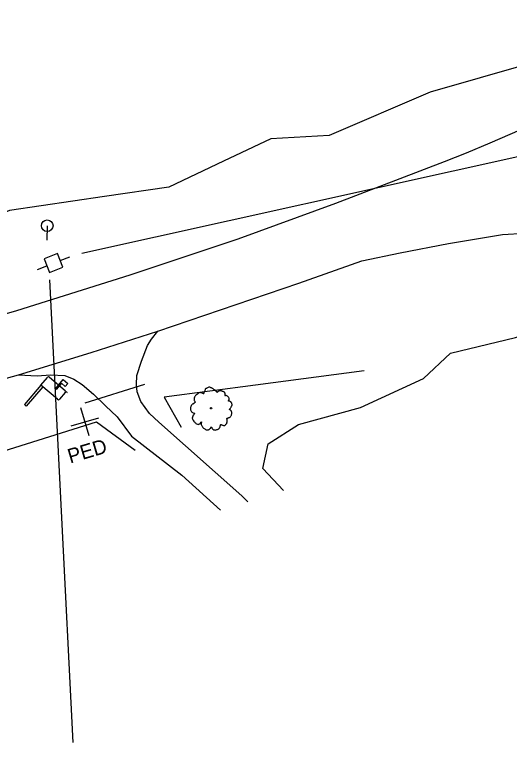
# Model space of a CAD drawing. Extents: x 2076109 to 2080761, y 592812 to 596750.
# Drawn here: x 2076543.2 to 2076714.3, y 595263.5 to 595514.8 of the extents above; entities that cross this region are included whole.
import ezdxf

# ---------------------------------------------------------------- set-up
doc = ezdxf.new("R2010")
doc.units = 0
for name, color, linetype in [('RD_EX_BldgApp', 7, 'Continuous'), ('RD_EX_DR_Pipe', 7, 'Continuous'), ('RD_EX_Driveway', 7, 'Continuous'), ('RD_EX_Fence_Other', 7, 'Continuous'), ('RD_EX_Misc', 7, 'Continuous'), ('RD_EX_Misc_txCode', 7, 'Continuous'), ('RD_EX_Road', 7, 'Continuous'), ('RD_EX_UT', 7, 'Continuous'), ('RD_EX_VEG', 7, 'Continuous')]:
    doc.layers.add(name, color=color, linetype=linetype)

msp = doc.modelspace()

# ---------------------------------------------------------------- linework, layer by layer
at = {"layer": 'RD_EX_BldgApp'}
for p, q in [((2076552.33, 595386.83), (2076554.6, 595389.5)), ((2076552.33, 595386.83), (2076554.6, 595389.5)), ((2076555.3, 595389.55), (2076560.69, 595384.98)), ((2076555.3, 595389.55), (2076560.69, 595384.98)), ((2076557.35, 595385.57), (2076560.06, 595388.76)), ((2076557.35, 595385.57), (2076560.06, 595388.76)), ((2076560.06, 595388.76), (2076561.63, 595387.43)), ((2076560.06, 595388.76), (2076561.63, 595387.43)), ((2076552.33, 595386.83), (2076546.62, 595380.11)), ((2076552.33, 595386.83), (2076546.62, 595380.11)), ((2076552.97, 595386.29), (2076547.26, 595379.57)), ((2076552.97, 595386.29), (2076547.26, 595379.57)), ((2076558.1, 595381.93), (2076552.33, 595386.83)), ((2076558.1, 595381.93), (2076552.33, 595386.83)), ((2076557.64, 595385.32), (2076557.35, 595385.57)), ((2076557.64, 595385.32), (2076557.35, 595385.57)), ((2076559.48, 595387.48), (2076557.64, 595385.32)), ((2076559.48, 595387.48), (2076557.64, 595385.32)), ((2076560.75, 595386.4), (2076559.48, 595387.48)), ((2076560.75, 595386.4), (2076559.48, 595387.48)), ((2076561.63, 595387.43), (2076560.75, 595386.4)), ((2076561.63, 595387.43), (2076560.75, 595386.4)), ((2076560.74, 595384.27), (2076558.8, 595381.99)), ((2076560.74, 595384.27), (2076558.8, 595381.99)), ((2076560.74, 595384.27), (2076561.07, 595384.65)), ((2076560.74, 595384.27), (2076561.07, 595384.65)), ((2076561.07, 595384.65), (2076561.45, 595384.33)), ((2076561.07, 595384.65), (2076561.45, 595384.33)), ((2076561.45, 595384.33), (2076561.29, 595384.14)), ((2076561.45, 595384.33), (2076561.29, 595384.14)), ((2076546.62, 595380.11), (2076547.26, 595379.57)), ((2076546.62, 595380.11), (2076547.26, 595379.57))]:
    msp.add_line(p, q, dxfattribs=at)
for centre, start, end in [((2076554.98, 595389.17), 49.6274, 139.6274), ((2076554.98, 595389.17), 49.6274, 139.6274), ((2076560.36, 595384.6), 319.6274, 49.6274), ((2076560.36, 595384.6), 319.6274, 49.6274), ((2076558.42, 595382.31), 229.6274, 319.6274), ((2076558.42, 595382.31), 229.6274, 319.6274)]:
    msp.add_arc(centre, 0.5, start, end, dxfattribs=at)
at = {"layer": 'RD_EX_DR_Pipe'}
msp.add_line((2076567.58, 595380.75), (2076588.2, 595387.21), dxfattribs=at)
msp.add_line((2076567.58, 595380.75), (2076588.2, 595387.21), dxfattribs=at)
at = {"layer": 'RD_EX_Driveway'}
msp.add_line((2076621.8, 595348.66), (2076623.83, 595346.57), dxfattribs=at)
msp.add_line((2076621.8, 595348.66), (2076623.83, 595346.57), dxfattribs=at)
for points in [[(2076621.8, 595348.66), (2076593.12, 595374.05), (2076589.9, 595376.98), (2076586.89, 595381.15), (2076585.6, 595384.51), (2076585.32, 595387.06), (2076585.46, 595390.21), (2076587.11, 595395.1), (2076589.17, 595400.48), (2076590.53, 595402.7), (2076592.75, 595405.46)], [(2076621.8, 595348.66), (2076593.12, 595374.05), (2076589.9, 595376.98), (2076586.89, 595381.15), (2076585.6, 595384.51), (2076585.32, 595387.06), (2076585.46, 595390.21), (2076587.11, 595395.1), (2076589.17, 595400.48), (2076590.53, 595402.7), (2076592.75, 595405.46)], [(2076544.59, 595390.37), (2076551.01, 595389.99), (2076555.66, 595390.36), (2076560.64, 595390.19), (2076563.66, 595388.87), (2076566.6, 595387.01), (2076570.56, 595383.69), (2076574.69, 595379.72), (2076578.65, 595375.85), (2076583.62, 595369.22), (2076601.04, 595355.7), (2076614.37, 595343.62)], [(2076544.59, 595390.37), (2076551.01, 595389.99), (2076555.66, 595390.36), (2076560.64, 595390.19), (2076563.66, 595388.87), (2076566.6, 595387.01), (2076570.56, 595383.69), (2076574.69, 595379.72), (2076578.65, 595375.85), (2076583.62, 595369.22), (2076601.04, 595355.7), (2076614.37, 595343.62)]]:
    msp.add_lwpolyline(points, dxfattribs=at)
at = {"layer": 'RD_EX_Fence_Other'}
for points in [[(2076664.12, 595391.78), (2076626.56, 595386.87), (2076594.95, 595382.67), (2076600.79, 595372.35)], [(2076664.12, 595391.78), (2076626.56, 595386.87), (2076594.95, 595382.67), (2076600.79, 595372.35)], [(2076413.91, 595332.33), (2076446.57, 595337.77), (2076456.21, 595339.99), (2076485.43, 595347.34), (2076504.69, 595353.19), (2076571.51, 595374.19), (2076584.94, 595364.39)], [(2076413.91, 595332.33), (2076446.57, 595337.77), (2076456.21, 595339.99), (2076485.43, 595347.34), (2076504.69, 595353.19), (2076571.51, 595374.19), (2076584.94, 595364.39)]]:
    msp.add_lwpolyline(points, dxfattribs=at)
at = {"layer": 'RD_EX_Misc'}
for p, q in [((2076569, 595369.35), (2076566.17, 595378.94)), ((2076569, 595369.35), (2076566.17, 595378.94)), ((2076562.79, 595372.73), (2076572.38, 595375.56)), ((2076562.79, 595372.73), (2076572.38, 595375.56))]:
    msp.add_line(p, q, dxfattribs=at)
at = {"layer": 'RD_EX_Road'}
for points in [[(2076707.59, 595470.49), (2076721.43, 595476.47)], [(2076707.59, 595470.49), (2076721.43, 595476.47)], [(2076404.77, 595376.23), (2076425.66, 595381.19), (2076454.7, 595388.18), (2076480.11, 595394.8), (2076514.19, 595403.96), (2076543.98, 595412.58), (2076583.19, 595424.9), (2076620.49, 595437.36), (2076654.29, 595449.62), (2076691.86, 595464.03), (2076699.44, 595467.03), (2076707.59, 595470.49)], [(2076404.77, 595376.23), (2076425.66, 595381.19), (2076454.7, 595388.18), (2076480.11, 595394.8), (2076514.19, 595403.96), (2076543.98, 595412.58), (2076583.19, 595424.9), (2076620.49, 595437.36), (2076654.29, 595449.62), (2076691.86, 595464.03), (2076699.44, 595467.03), (2076707.59, 595470.49)], [(2076409.15, 595355.14), (2076418.82, 595357.38), (2076452.18, 595365.54), (2076478.97, 595372.37), (2076513.39, 595381.71), (2076544.59, 595390.37), (2076569.72, 595398.06), (2076592.75, 595405.46), (2076641.5, 595422.06), (2076663.28, 595429.78), (2076676.52, 595432.55), (2076693.19, 595435.72), (2076711.91, 595438.8), (2076719.56, 595439.35)], [(2076409.15, 595355.14), (2076418.82, 595357.38), (2076452.18, 595365.54), (2076478.97, 595372.37), (2076513.39, 595381.71), (2076544.59, 595390.37), (2076569.72, 595398.06), (2076592.75, 595405.46), (2076641.5, 595422.06), (2076663.28, 595429.78), (2076676.52, 595432.55), (2076693.19, 595435.72), (2076711.91, 595438.8), (2076719.56, 595439.35)]]:
    msp.add_lwpolyline(points, dxfattribs=at)
at = {"layer": 'RD_EX_UT'}
for p, q in [((2076566.44, 595432.36), (2076937.84, 595514.77)), ((2076566.44, 595432.36), (2076937.84, 595514.77)), ((2076554.51, 595441.88), (2076554.35, 595436.88)), ((2076554.51, 595441.88), (2076554.35, 595436.88)), ((2076558.08, 595432.23), (2076553.43, 595430.4)), ((2076558.08, 595432.23), (2076553.43, 595430.4)), ((2076559.92, 595427.58), (2076558.08, 595432.23)), ((2076559.92, 595427.58), (2076558.08, 595432.23)), ((2076558.95, 595429.82), (2076562.34, 595431.16)), ((2076558.95, 595429.82), (2076562.34, 595431.16)), ((2076553.43, 595430.4), (2076555.27, 595425.75)), ((2076553.43, 595430.4), (2076555.27, 595425.75)), ((2076551.18, 595426.75), (2076554.4, 595428.03)), ((2076551.18, 595426.75), (2076554.4, 595428.03)), ((2076555.27, 595425.75), (2076559.92, 595427.58)), ((2076555.27, 595425.75), (2076559.92, 595427.58)), ((2076555.28, 595423.13), (2076563.41, 595263.47)), ((2076555.28, 595423.13), (2076563.41, 595263.47))]:
    msp.add_line(p, q, dxfattribs=at)
msp.add_circle((2076554.51, 595441.88), 2, dxfattribs=at)
msp.add_circle((2076554.51, 595441.88), 2, dxfattribs=at)
at = {"layer": 'RD_EX_VEG'}
for points in [[(2076721.44, 595497.84), (2076686.85, 595487.97), (2076651.97, 595472.98), (2076631.79, 595471.84), (2076615.46, 595464.14), (2076596.55, 595455.13), (2076574.34, 595452), (2076541.43, 595447.14), (2076519.2, 595437.7), (2076507.89, 595433.3), (2076488.78, 595429.26), (2076474.26, 595438.65), (2076467.23, 595441.67), (2076458.17, 595436.65), (2076443.11, 595431.74), (2076430.14, 595424.51), (2076425.47, 595425.53), (2076421.37, 595431.78), (2076421.26, 595440.12)], [(2076721.44, 595497.84), (2076686.85, 595487.97), (2076651.97, 595472.98), (2076631.79, 595471.84), (2076615.46, 595464.14), (2076596.55, 595455.13), (2076574.34, 595452), (2076541.43, 595447.14), (2076519.2, 595437.7), (2076507.89, 595433.3), (2076488.78, 595429.26), (2076474.26, 595438.65), (2076467.23, 595441.67), (2076458.17, 595436.65), (2076443.11, 595431.74), (2076430.14, 595424.51), (2076425.47, 595425.53), (2076421.37, 595431.78), (2076421.26, 595440.12)], [(2076636.23, 595350.44), (2076629.1, 595358.09), (2076630.91, 595366.51), (2076641.43, 595373.25), (2076662.8, 595379.06), (2076684.62, 595389.11), (2076693.88, 595397.83), (2076716.37, 595403.24), (2076739.1, 595410.66), (2076755.46, 595414.28), (2076767.4, 595412.06), (2076793.28, 595417.54), (2076814.44, 595417.26), (2076822.78, 595411.67)], [(2076636.23, 595350.44), (2076629.1, 595358.09), (2076630.91, 595366.51), (2076641.43, 595373.25), (2076662.8, 595379.06), (2076684.62, 595389.11), (2076693.88, 595397.83), (2076716.37, 595403.24), (2076739.1, 595410.66), (2076755.46, 595414.28), (2076767.4, 595412.06), (2076793.28, 595417.54), (2076814.44, 595417.26), (2076822.78, 595411.67)]]:
    msp.add_lwpolyline(points, dxfattribs=at)
for centre, radius in [((2076611.17, 595378.87), 0.25), ((2076611.17, 595378.87), 0.25), ((2076611.15, 595378.87), 0.0001), ((2076611.15, 595378.87), 0.0001)]:
    msp.add_circle(centre, radius, dxfattribs=at)
for points in [[(2076615.91, 595384.25), (2076615.7, 595384.46), (2076615.39, 595384.6), (2076615.13, 595384.68), (2076614.91, 595384.77), (2076614.67, 595384.84), (2076614.33, 595384.9), (2076614.03, 595384.89), (2076613.78, 595384.78), (2076613.59, 595384.65), (2076613.38, 595384.47), (2076613.26, 595384.33), (2076613.15, 595384.4), (2076613.05, 595384.51), (2076612.91, 595384.73), (2076612.72, 595384.89), (2076612.53, 595385.06), (2076612.25, 595385.26), (2076611.98, 595385.49), (2076611.74, 595385.63), (2076611.46, 595385.8), (2076611.09, 595385.95), (2076610.75, 595386.08), (2076610.35, 595386.09), (2076609.86, 595385.89), (2076609.53, 595385.7), (2076609.26, 595385.61), (2076609.08, 595385.17), (2076608.99, 595384.79), (2076608.88, 595384.62), (2076608.66, 595384.25), (2076608.59, 595384.01), (2076608.56, 595383.78), (2076608.48, 595383.81), (2076608.16, 595384.01), (2076607.87, 595384.13), (2076607.4, 595384.23), (2076607.09, 595384.21), (2076606.8, 595384.02), (2076606.55, 595383.77), (2076606.35, 595383.69), (2076606.11, 595383.53), (2076606.04, 595383.48), (2076605.8, 595383.27), (2076605.58, 595382.86), (2076605.37, 595382.58), (2076605.32, 595382.33), (2076605.32, 595382.1), (2076605.3, 595381.79), (2076605.45, 595381.36), (2076605.64, 595381.08), (2076605.77, 595380.93), (2076605.32, 595380.66), (2076605.05, 595380.43), (2076604.7, 595380.2), (2076604.65, 595380.15), (2076604.3, 595379.82), (2076604.21, 595379.47), (2076604.02, 595379.14), (2076604.01, 595378.85), (2076604.02, 595378.45), (2076604.13, 595378.06), (2076604.43, 595377.65), (2076604.75, 595377.41), (2076605.3, 595377.17), (2076605.54, 595377.06), (2076605.4, 595376.94), (2076605.18, 595376.64), (2076604.9, 595376.32), (2076604.81, 595375.97), (2076604.71, 595375.7), (2076604.66, 595375.41), (2076604.76, 595375.03), (2076605.02, 595374.72), (2076605.24, 595374.33), (2076605.54, 595373.98), (2076605.9, 595373.63), (2076606.46, 595373.36), (2076606.75, 595373.28), (2076606.94, 595373.35), (2076607.33, 595373.5), (2076607.44, 595373.71), (2076607.85, 595374.15), (2076607.81, 595373.95), (2076607.72, 595373.57), (2076607.9, 595373.02), (2076608.09, 595372.62), (2076608.36, 595372.2), (2076608.54, 595371.95), (2076608.95, 595371.7), (2076609.28, 595371.51), (2076609.65, 595371.37), (2076610.06, 595371.38), (2076610.37, 595371.48), (2076610.58, 595371.66), (2076610.88, 595371.89), (2076611.03, 595371.99)], [(2076615.91, 595384.25), (2076615.7, 595384.46), (2076615.39, 595384.6), (2076615.13, 595384.68), (2076614.91, 595384.77), (2076614.67, 595384.84), (2076614.33, 595384.9), (2076614.03, 595384.89), (2076613.78, 595384.78), (2076613.59, 595384.65), (2076613.38, 595384.47), (2076613.26, 595384.33), (2076613.15, 595384.4), (2076613.05, 595384.51), (2076612.91, 595384.73), (2076612.72, 595384.89), (2076612.53, 595385.06), (2076612.25, 595385.26), (2076611.98, 595385.49), (2076611.74, 595385.63), (2076611.46, 595385.8), (2076611.09, 595385.95), (2076610.75, 595386.08), (2076610.35, 595386.09), (2076609.86, 595385.89), (2076609.53, 595385.7), (2076609.26, 595385.61), (2076609.08, 595385.17), (2076608.99, 595384.79), (2076608.88, 595384.62), (2076608.66, 595384.25), (2076608.59, 595384.01), (2076608.56, 595383.78), (2076608.48, 595383.81), (2076608.16, 595384.01), (2076607.87, 595384.13), (2076607.4, 595384.23), (2076607.09, 595384.21), (2076606.8, 595384.02), (2076606.55, 595383.77), (2076606.35, 595383.69), (2076606.11, 595383.53), (2076606.04, 595383.48), (2076605.8, 595383.27), (2076605.58, 595382.86), (2076605.37, 595382.58), (2076605.32, 595382.33), (2076605.32, 595382.1), (2076605.3, 595381.79), (2076605.45, 595381.36), (2076605.64, 595381.08), (2076605.77, 595380.93), (2076605.32, 595380.66), (2076605.05, 595380.43), (2076604.7, 595380.2), (2076604.65, 595380.15), (2076604.3, 595379.82), (2076604.21, 595379.47), (2076604.02, 595379.14), (2076604.01, 595378.85), (2076604.02, 595378.45), (2076604.13, 595378.06), (2076604.43, 595377.65), (2076604.75, 595377.41), (2076605.3, 595377.17), (2076605.54, 595377.06), (2076605.4, 595376.94), (2076605.18, 595376.64), (2076604.9, 595376.32), (2076604.81, 595375.97), (2076604.71, 595375.7), (2076604.66, 595375.41), (2076604.76, 595375.03), (2076605.02, 595374.72), (2076605.24, 595374.33), (2076605.54, 595373.98), (2076605.9, 595373.63), (2076606.46, 595373.36), (2076606.75, 595373.28), (2076606.94, 595373.35), (2076607.33, 595373.5), (2076607.44, 595373.71), (2076607.85, 595374.15), (2076607.81, 595373.95), (2076607.72, 595373.57), (2076607.9, 595373.02), (2076608.09, 595372.62), (2076608.36, 595372.2), (2076608.54, 595371.95), (2076608.95, 595371.7), (2076609.28, 595371.51), (2076609.65, 595371.37), (2076610.06, 595371.38), (2076610.37, 595371.48), (2076610.58, 595371.66), (2076610.88, 595371.89), (2076611.03, 595371.99)], [(2076611.03, 595371.99), (2076611.09, 595372.18), (2076611.21, 595372.4), (2076611.26, 595372.33), (2076611.36, 595372.18), (2076611.48, 595371.91), (2076611.61, 595371.7), (2076611.87, 595371.51), (2076612.15, 595371.41), (2076612.67, 595371.33), (2076613.18, 595371.51), (2076613.65, 595371.64), (2076613.92, 595371.84), (2076614.03, 595372.04), (2076614.33, 595372.44), (2076614.34, 595372.76), (2076614.38, 595372.89), (2076614.57, 595373.25), (2076614.66, 595373.24), (2076614.9, 595373.1), (2076615.26, 595372.96), (2076615.55, 595372.87), (2076615.84, 595372.86), (2076616.04, 595372.98), (2076616.28, 595373.3), (2076616.58, 595373.58), (2076616.62, 595373.74), (2076616.64, 595373.92), (2076616.71, 595374.12), (2076616.7, 595374.33), (2076616.72, 595374.51), (2076616.7, 595374.65), (2076616.71, 595374.85), (2076616.65, 595375.05), (2076616.57, 595375.19), (2076616.63, 595375.34), (2076616.88, 595375.39), (2076616.98, 595375.44), (2076617.14, 595375.59), (2076617.54, 595375.71), (2076617.84, 595375.98), (2076618.08, 595376.34), (2076618.22, 595376.58), (2076618.28, 595376.89), (2076618.29, 595377.21), (2076618.31, 595377.42), (2076618.25, 595377.63), (2076618.09, 595377.94), (2076617.93, 595378.14), (2076617.66, 595378.36), (2076617.54, 595378.53), (2076617.59, 595378.55), (2076617.69, 595378.67), (2076617.87, 595378.88), (2076618.1, 595379.27), (2076618.31, 595379.74), (2076618.33, 595379.76), (2076618.42, 595380.02), (2076618.37, 595380.32), (2076618.31, 595380.51), (2076618.23, 595380.73), (2076618.06, 595380.91), (2076617.83, 595381.11), (2076617.59, 595381.25), (2076617.37, 595381.3), (2076617.16, 595381.32), (2076617.2, 595381.48), (2076617.32, 595381.77), (2076617.38, 595381.92), (2076617.37, 595382.15), (2076617.33, 595382.45), (2076617.07, 595382.84), (2076616.55, 595383.18), (2076616.19, 595383.22), (2076615.96, 595383.19), (2076616, 595383.32), (2076615.98, 595383.6), (2076616.02, 595383.8), (2076615.97, 595384), (2076615.92, 595384.18), (2076615.87, 595384.28)], [(2076611.03, 595371.99), (2076611.09, 595372.18), (2076611.21, 595372.4), (2076611.26, 595372.33), (2076611.36, 595372.18), (2076611.48, 595371.91), (2076611.61, 595371.7), (2076611.87, 595371.51), (2076612.15, 595371.41), (2076612.67, 595371.33), (2076613.18, 595371.51), (2076613.65, 595371.64), (2076613.92, 595371.84), (2076614.03, 595372.04), (2076614.33, 595372.44), (2076614.34, 595372.76), (2076614.38, 595372.89), (2076614.57, 595373.25), (2076614.66, 595373.24), (2076614.9, 595373.1), (2076615.26, 595372.96), (2076615.55, 595372.87), (2076615.84, 595372.86), (2076616.04, 595372.98), (2076616.28, 595373.3), (2076616.58, 595373.58), (2076616.62, 595373.74), (2076616.64, 595373.92), (2076616.71, 595374.12), (2076616.7, 595374.33), (2076616.72, 595374.51), (2076616.7, 595374.65), (2076616.71, 595374.85), (2076616.65, 595375.05), (2076616.57, 595375.19), (2076616.63, 595375.34), (2076616.88, 595375.39), (2076616.98, 595375.44), (2076617.14, 595375.59), (2076617.54, 595375.71), (2076617.84, 595375.98), (2076618.08, 595376.34), (2076618.22, 595376.58), (2076618.28, 595376.89), (2076618.29, 595377.21), (2076618.31, 595377.42), (2076618.25, 595377.63), (2076618.09, 595377.94), (2076617.93, 595378.14), (2076617.66, 595378.36), (2076617.54, 595378.53), (2076617.59, 595378.55), (2076617.69, 595378.67), (2076617.87, 595378.88), (2076618.1, 595379.27), (2076618.31, 595379.74), (2076618.33, 595379.76), (2076618.42, 595380.02), (2076618.37, 595380.32), (2076618.31, 595380.51), (2076618.23, 595380.73), (2076618.06, 595380.91), (2076617.83, 595381.11), (2076617.59, 595381.25), (2076617.37, 595381.3), (2076617.16, 595381.32), (2076617.2, 595381.48), (2076617.32, 595381.77), (2076617.38, 595381.92), (2076617.37, 595382.15), (2076617.33, 595382.45), (2076617.07, 595382.84), (2076616.55, 595383.18), (2076616.19, 595383.22), (2076615.96, 595383.19), (2076616, 595383.32), (2076615.98, 595383.6), (2076616.02, 595383.8), (2076615.97, 595384), (2076615.92, 595384.18), (2076615.87, 595384.28)]]:
    msp.add_spline(points, degree=3, dxfattribs=at)

# ---------------------------------------------------------------- texts
at = {"layer": 'RD_EX_Misc_txCode'}
msp.add_text('PED', height=5, rotation=16.4356, dxfattribs=at).set_placement((2076562.43, 595359.75))
msp.add_text('PED', height=5, rotation=16.4356, dxfattribs=at).set_placement((2076562.43, 595359.75))

doc.saveas('drawing.dxf')
